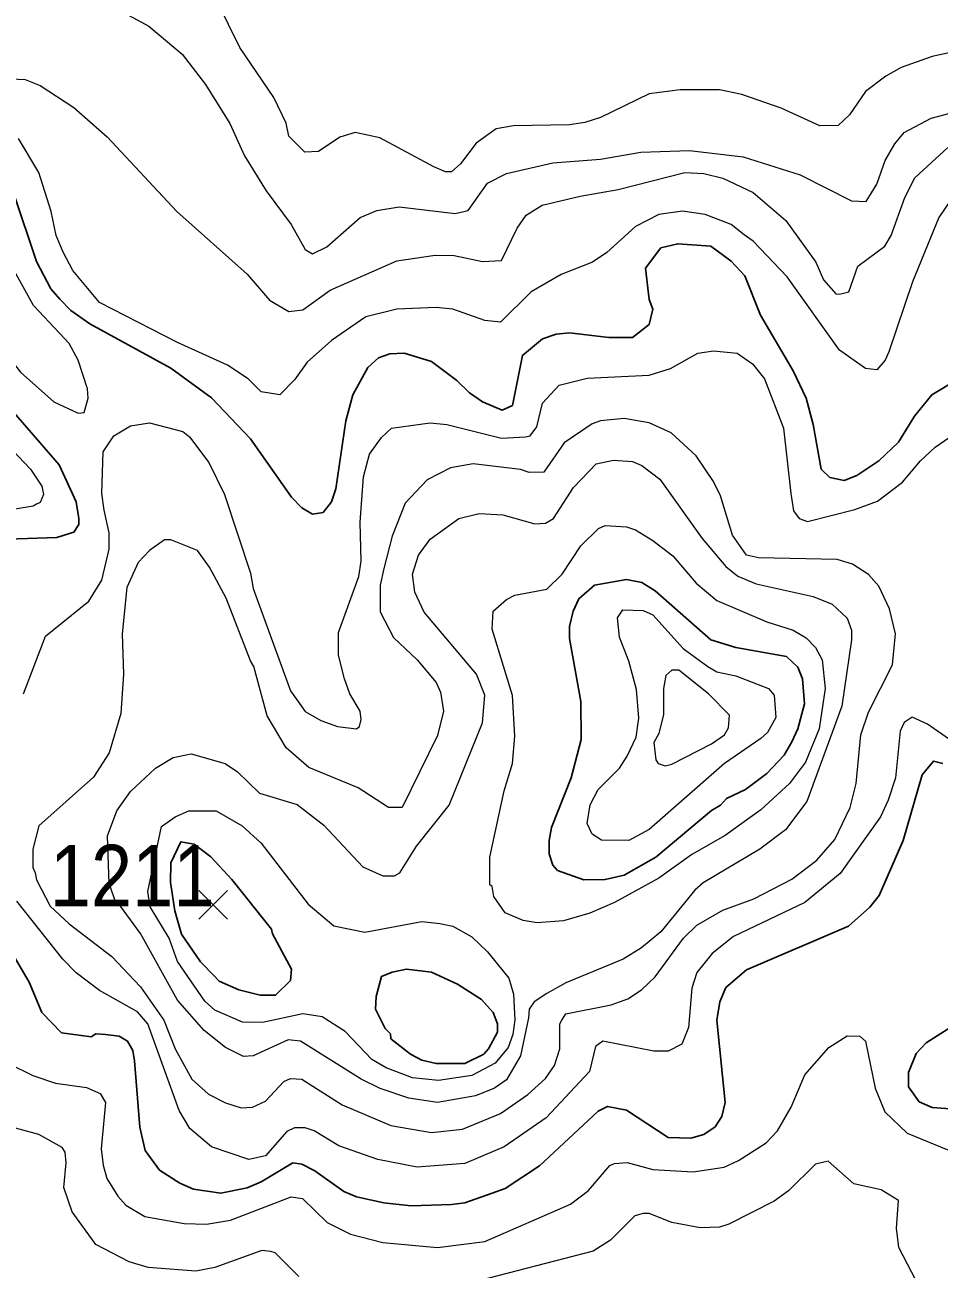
# Model space of a CAD drawing. Extents: x 423 to 448.8, y 7456.3 to 7484.
# Drawn here: x 429.044 to 430.233, y 7478.283 to 7479.901 of the extents above; entities that cross this region are included whole.
import ezdxf
from ezdxf.enums import TextEntityAlignment as Align

# ---------------------------------------------------------------- set-up
doc = ezdxf.new("R2010")
doc.units = 0
doc.header["$LTSCALE"] = 0.032
for name, color, linetype, lineweight in [('1', 7, 'Continuous', 25), ('2', 7, 'Continuous', 13), ('21', 7, 'Continuous', 25)]:
    doc.layers.add(name, color=color, linetype=linetype, lineweight=lineweight)
doc.layers.add('61', color=7, linetype='Continuous')

msp = doc.modelspace()

# ---------------------------------------------------------------- linework, layer by layer
at = {"layer": '1'}
for points in [[(429.3377, 7479.3629), (429.2867, 7479.4163), (429.2341, 7479.4549), (429.1289, 7479.5122), (429.1042, 7479.5299), (429.0895, 7479.5446), (429.0779, 7479.5578), (429.0593, 7479.5934), (429.0299, 7479.6816)], [(430.2597, 7479.4418), (430.2234, 7479.4201), (430.2009, 7479.3923), (430.1801, 7479.3583), (430.1546, 7479.3343), (430.1259, 7479.3149), (430.1097, 7479.3087), (430.0911, 7479.3126), (430.0795, 7479.3235), (430.0695, 7479.3815), (430.0602, 7479.4155), (430.0431, 7479.4511), (430.0006, 7479.5238), (429.9805, 7479.5748), (429.9627, 7479.5941), (429.9364, 7479.6135), (429.8931, 7479.6166), (429.8714, 7479.6112), (429.8513, 7479.5849), (429.856, 7479.5439), (429.8606, 7479.5315), (429.856, 7479.5114), (429.8343, 7479.4944), (429.8034, 7479.4944), (429.7524, 7479.5006), (429.7353, 7479.499), (429.7175, 7479.4928), (429.6912, 7479.4712), (429.6781, 7479.4062), (429.6649, 7479.4), (429.6394, 7479.4109), (429.6224, 7479.4225), (429.6061, 7479.4387), (429.5729, 7479.4635), (429.5373, 7479.4743), (429.5188, 7479.4735), (429.504, 7479.4681), (429.4901, 7479.4557), (429.4708, 7479.4202), (429.4615, 7479.3861), (429.4484, 7479.2979), (429.443, 7479.2809), (429.4321, 7479.267), (429.4182, 7479.2647), (429.4043, 7479.2732), (429.3911, 7479.2871), (429.3377, 7479.3629)], [(429.0044, 7479.4263), (429.0887, 7479.3289), (429.1111, 7479.2809), (429.1142, 7479.2593), (429.1142, 7479.2515), (429.1081, 7479.2415), (429.1034, 7479.2399), (429.0856, 7479.2345), (429.0222, 7479.2322)], [(429.6688, 7478.3876), (429.7136, 7478.4169), (429.7895, 7478.4881), (429.8019, 7478.4943), (429.8266, 7478.4896), (429.8808, 7478.4541), (429.9101, 7478.4533), (429.9272, 7478.458), (429.9418, 7478.468), (429.9504, 7478.4812), (429.955, 7478.4997), (429.9442, 7478.6065), (429.948, 7478.6304), (429.9557, 7478.649), (429.9828, 7478.6722), (430.1151, 7478.7287), (430.1429, 7478.7534), (430.1553, 7478.7689), (430.1863, 7478.8401), (430.211, 7478.9259), (430.2257, 7478.9437), (430.2381, 7478.9406)], [(429.0291, 7478.6916), (429.05, 7478.656), (429.0663, 7478.6165), (429.0918, 7478.5902), (429.1305, 7478.5848), (429.1367, 7478.5886), (429.1491, 7478.5879), (429.1668, 7478.5856), (429.1777, 7478.5794), (429.1846, 7478.567), (429.1869, 7478.5539), (429.1939, 7478.4673), (429.2008, 7478.4371), (429.2194, 7478.4115), (429.2457, 7478.3945), (429.2635, 7478.3868), (429.2991, 7478.3814), (429.3331, 7478.3883), (429.3517, 7478.3961), (429.3927, 7478.4208), (429.4043, 7478.4193), (429.4213, 7478.4108), (429.4592, 7478.3837), (429.4755, 7478.3767), (429.511, 7478.369), (429.5466, 7478.3651), (429.5992, 7478.3667), (429.6162, 7478.369), (429.6518, 7478.3814), (429.6688, 7478.3876)], [(430.2628, 7478.6065), (430.2164, 7478.577), (430.2032, 7478.5632), (430.1932, 7478.5384), (430.1932, 7478.5198), (430.2072, 7478.5005), (430.2242, 7478.4928), (430.2597, 7478.4904)]]:
    msp.add_lwpolyline(points, dxfattribs=at)
for points in [[(429.7988, 7478.7897), (429.8235, 7478.7952), (429.8645, 7478.8184), (429.9372, 7478.8795), (429.9488, 7478.8864), (429.9565, 7478.8949), (429.9813, 7478.9066), (430.0091, 7478.9274), (430.0315, 7478.9514), (430.0416, 7478.9685), (430.0494, 7478.9855), (430.0579, 7479.018), (430.0555, 7479.0504), (430.0494, 7479.0659), (430.0346, 7479.0798), (429.9689, 7479.0914), (429.9364, 7479.1015), (429.8637, 7479.1649), (429.8467, 7479.1757), (429.8266, 7479.1796), (429.7848, 7479.1726), (429.7647, 7479.1548), (429.757, 7479.1386), (429.7523, 7479.1185), (429.7523, 7479.103), (429.767, 7479.021), (429.7678, 7478.9715), (429.7547, 7478.922), (429.7291, 7478.8571), (429.726, 7478.8401), (429.726, 7478.823), (429.7307, 7478.8083), (429.7369, 7478.8014), (429.7709, 7478.789)], [(429.3663, 7478.719), (429.3648, 7478.7248), (429.3135, 7478.7894), (429.2862, 7478.819), (429.2645, 7478.8357), (429.2472, 7478.8386), (429.2342, 7478.8111), (429.2335, 7478.7858), (429.2393, 7478.749), (429.2481, 7478.7186), (429.2728, 7478.6823), (429.2898, 7478.6645), (429.2968, 7478.6575), (429.3223, 7478.6459), (429.3502, 7478.6389), (429.3703, 7478.6389), (429.3896, 7478.6583), (429.3911, 7478.673)], [(429.5219, 7478.6691), (429.5404, 7478.673), (429.5729, 7478.6691), (429.6069, 7478.6536), (429.6378, 7478.6335), (429.6533, 7478.6165), (429.6588, 7478.6018), (429.6588, 7478.591), (429.6471, 7478.5693), (429.641, 7478.5624), (429.6162, 7478.55), (429.5791, 7478.55), (429.5605, 7478.5546), (429.5458, 7478.5624), (429.5203, 7478.5825), (429.5195, 7478.5887), (429.5126, 7478.5956), (429.5002, 7478.6211), (429.501, 7478.6374), (429.508, 7478.6635)]]:
    msp.add_lwpolyline(points, close=True, dxfattribs=at)
at = {"layer": '2'}
for points in [[(430.286, 7479.8734), (430.2242, 7479.8602), (430.1839, 7479.8456), (430.1638, 7479.8347), (430.1375, 7479.8146), (430.1166, 7479.7844), (430.102, 7479.7705), (430.078, 7479.7698), (430.0277, 7479.793), (429.9767, 7479.8107), (429.9473, 7479.8169), (429.8962, 7479.8169), (429.856, 7479.8115), (429.7926, 7479.7806), (429.7725, 7479.7744), (429.7524, 7479.7713), (429.6797, 7479.7698), (429.6572, 7479.7659), (429.6309, 7479.7473), (429.6108, 7479.7203), (429.5992, 7479.7102), (429.5914, 7479.7102), (429.576, 7479.7164), (429.5056, 7479.7543), (429.4739, 7479.7612), (429.4538, 7479.755), (429.426, 7479.7365), (429.4081, 7479.7357), (429.3873, 7479.7566), (429.3842, 7479.7736), (429.3679, 7479.8069), (429.3238, 7479.8719), (429.279, 7479.9631)], [(429.1583, 7479.9252), (429.2055, 7479.8997), (429.2488, 7479.8633), (429.279, 7479.8239), (429.3107, 7479.7729), (429.33, 7479.7311), (429.3579, 7479.6854), (429.3903, 7479.6414), (429.4089, 7479.6089), (429.4182, 7479.6034), (429.4367, 7479.6127), (429.4801, 7479.6506), (429.5018, 7479.6599), (429.5311, 7479.6646), (429.6039, 7479.656), (429.6208, 7479.6599), (429.6456, 7479.6955), (429.6704, 7479.7079), (429.7307, 7479.7218), (429.7926, 7479.7264), (429.8452, 7479.7357), (429.9086, 7479.738), (429.9782, 7479.7295), (430.0525, 7479.7063), (430.119, 7479.6723), (430.1383, 7479.6715), (430.1522, 7479.694), (430.163, 7479.7249), (430.1754, 7479.7466), (430.1878, 7479.7612), (430.2226, 7479.7798), (430.3464, 7479.8123)], [(429.0168, 7479.8316), (429.0446, 7479.8301), (429.064, 7479.8223), (429.108, 7479.7937), (429.1513, 7479.7558), (429.2419, 7479.6583), (429.3331, 7479.5771), (429.3625, 7479.5431), (429.3873, 7479.5284), (429.4058, 7479.5307), (429.4414, 7479.5563), (429.5281, 7479.5942), (429.5776, 7479.6019), (429.6023, 7479.6011), (429.6394, 7479.5934), (429.6642, 7479.5949), (429.6843, 7479.6367), (429.6959, 7479.6537), (429.7168, 7479.6669), (429.7663, 7479.6785), (429.8158, 7479.687), (429.9024, 7479.7094), (429.9272, 7479.7079), (429.9519, 7479.7017)], [(430.2481, 7479.6738), (430.2326, 7479.6506), (430.1986, 7479.5671), (430.1677, 7479.4758), (430.163, 7479.465), (430.1522, 7479.4526), (430.1375, 7479.4541), (430.1035, 7479.4781), (430.0354, 7479.5733), (429.9913, 7479.6197), (429.9797, 7479.6282), (429.9627, 7479.6414), (429.9287, 7479.6545), (429.8993, 7479.6591), (429.8684, 7479.6545), (429.8382, 7479.639), (429.8011, 7479.605), (429.7825, 7479.5926), (429.7415, 7479.5764), (429.7028, 7479.5539), (429.6626, 7479.5145), (429.6425, 7479.5168), (429.6008, 7479.5315), (429.5791, 7479.5338), (429.5281, 7479.5315), (429.4878, 7479.5214), (429.443, 7479.4905), (429.4112, 7479.4627), (429.395, 7479.4395), (429.3757, 7479.4201), (429.3517, 7479.424), (429.3346, 7479.441), (429.3076, 7479.4588), (429.2426, 7479.4882), (429.1413, 7479.54), (429.1065, 7479.5818), (429.0941, 7479.6058), (429.0848, 7479.6274), (429.0786, 7479.6584), (429.0624, 7479.7094), (429.0361, 7479.7535)], [(429.9519, 7479.7017), (429.9913, 7479.6831), (430.0339, 7479.6468), (430.0726, 7479.5926), (430.0826, 7479.5694), (430.0989, 7479.5516), (430.1035, 7479.5508), (430.1158, 7479.5539), (430.1274, 7479.5872), (430.1623, 7479.6135), (430.1708, 7479.6274), (430.1886, 7479.6769), (430.2017, 7479.7024), (430.2443, 7479.7419)], [(429.0423, 7479.0311), (429.0709, 7479.1061), (429.1274, 7479.1517), (429.1444, 7479.1788), (429.1537, 7479.2191), (429.1537, 7479.2407), (429.1475, 7479.2701), (429.1444, 7479.2918), (429.1459, 7479.3459), (429.1599, 7479.3668), (429.1815, 7479.3799), (429.2063, 7479.3838), (429.2496, 7479.3722), (429.2581, 7479.3652), (429.2836, 7479.332), (429.3037, 7479.2902), (429.3378, 7479.1881), (429.3409, 7479.168), (429.3896, 7479.035), (429.4089, 7479.0079), (429.429, 7478.9963), (429.4507, 7478.9886), (429.4754, 7478.9854), (429.4793, 7478.9885), (429.4816, 7478.9978), (429.4801, 7479.0087), (429.4669, 7479.0311), (429.46, 7479.0504), (429.4522, 7479.0814), (429.4522, 7479.1108), (429.4785, 7479.1835), (429.4816, 7479.2036), (429.4801, 7479.2546), (429.4847, 7479.3134), (429.4924, 7479.3428), (429.5079, 7479.3644), (429.5211, 7479.3768), (429.5714, 7479.3838), (429.593, 7479.3815), (429.6642, 7479.3637), (429.6951, 7479.3652), (429.7013, 7479.3668), (429.7098, 7479.3783), (429.7175, 7479.4093), (429.7392, 7479.4325), (429.7756, 7479.4418), (429.856, 7479.4456), (429.8838, 7479.4541), (429.9194, 7479.4743), (429.9395, 7479.4774), (429.9705, 7479.4743), (429.9905, 7479.4603), (430.006, 7479.441), (430.0308, 7479.3768), (430.0401, 7479.2918), (430.0439, 7479.2693), (430.0509, 7479.2593), (430.0617, 7479.2554), (430.1236, 7479.2708), (430.153, 7479.2817), (430.1854, 7479.3064), (430.2087, 7479.3343), (430.228, 7479.352), (430.2976, 7479.4)], [(429.8637, 7478.6629), (429.9008, 7478.7132), (429.9179, 7478.7302), (429.9519, 7478.7495), (429.9921, 7478.7643), (430.0416, 7478.7898), (430.0741, 7478.8145), (430.0973, 7478.8416), (430.1174, 7478.8834), (430.1252, 7478.9143), (430.1313, 7478.9777), (430.1414, 7479.0071), (430.1723, 7479.069), (430.1762, 7479.1092), (430.1685, 7479.1417), (430.1545, 7479.1711), (430.1414, 7479.1865), (430.1205, 7479.1997), (430.1004, 7479.2059), (429.9983, 7479.2082), (429.9828, 7479.2113), (429.9643, 7479.2376), (429.9488, 7479.2887), (429.9395, 7479.3072), (429.9171, 7479.3405), (429.8846, 7479.3706), (429.856, 7479.3838), (429.8235, 7479.3892), (429.7926, 7479.3861), (429.7817, 7479.3822), (429.7454, 7479.3575), (429.7191, 7479.3196), (429.6998, 7479.3188), (429.6889, 7479.3227), (429.6271, 7479.3304), (429.5977, 7479.325), (429.5675, 7479.3095), (429.5389, 7479.2793), (429.5219, 7479.2361), (429.511, 7479.1943), (429.5064, 7479.1726), (429.5064, 7479.1378), (429.5234, 7479.1045), (429.5543, 7479.0752), (429.5791, 7479.0458), (429.5845, 7479.0334), (429.5884, 7479.0087), (429.5806, 7478.9769), (429.535, 7478.8834), (429.5172, 7478.8834), (429.4778, 7478.9089), (429.4136, 7478.9352), (429.3841, 7478.9607), (429.3594, 7479.0025), (429.3419, 7479.0668), (429.3378, 7479.0739), (429.306, 7479.1556), (429.2844, 7479.1959), (429.2689, 7479.2175), (429.2341, 7479.2314), (429.2256, 7479.2314), (429.2062, 7479.2175), (429.1916, 7479.202), (429.1769, 7479.1696), (429.1707, 7479.1092), (429.1723, 7479.0566), (429.1692, 7479.0056), (429.1537, 7478.9545), (429.1336, 7478.9228), (429.0624, 7478.8594), (429.0547, 7478.8292), (429.0547, 7478.8052), (429.0578, 7478.7983), (429.0593, 7478.789), (429.0771, 7478.7549), (429.1018, 7478.7317), (429.1575, 7478.6892), (429.1947, 7478.6498), (429.2248, 7478.6065), (429.2395, 7478.5693), (429.2612, 7478.5299), (429.2828, 7478.5105), (429.3053, 7478.4989), (429.3254, 7478.4927), (429.3401, 7478.4935), (429.3571, 7478.5012), (429.3811, 7478.5268), (429.3896, 7478.5307), (429.4043, 7478.5299), (429.4568, 7478.4966), (429.5203, 7478.4695), (429.5729, 7478.4603), (429.6131, 7478.4649), (429.6626, 7478.485), (429.6982, 7478.5098), (429.7214, 7478.5306), (429.733, 7478.5477), (429.74, 7478.5693), (429.74, 7478.6018), (429.7423, 7478.6065), (429.7477, 7478.615)], [(429.0207, 7479.3559), (429.0516, 7479.3235), (429.0663, 7479.301), (429.0686, 7479.2902), (429.0639, 7479.2801), (429.0594, 7479.278), (429.0548, 7479.275), (429.0006, 7479.2662)], [(430.2814, 7478.9475), (430.218, 7478.9916), (430.1979, 7479.0009), (430.1878, 7478.9939), (430.1824, 7478.9824), (430.1762, 7478.922), (430.1669, 7478.8927), (430.1568, 7478.871), (430.1043, 7478.7975), (430.0586, 7478.7596), (429.9658, 7478.7155), (429.938, 7478.6931), (429.9179, 7478.6684), (429.9117, 7478.6482), (429.907, 7478.5972), (429.8985, 7478.5755), (429.8808, 7478.5662), (429.8622, 7478.5662), (429.7956, 7478.5794), (429.7863, 7478.5724), (429.7786, 7478.54), (429.7222, 7478.4796), (429.6673, 7478.4417), (429.6162, 7478.42), (429.5544, 7478.4154), (429.5033, 7478.4255), (429.4523, 7478.4432), (429.4205, 7478.4626), (429.4089, 7478.4664), (429.395, 7478.4664), (429.3849, 7478.4618), (429.3571, 7478.4301), (429.3354, 7478.4255), (429.2867, 7478.4417), (429.2589, 7478.4657), (429.245, 7478.4889)], [(429.245, 7478.4889), (429.2039, 7478.6018), (429.1908, 7478.6173), (429.1413, 7478.6451), (429.1111, 7478.6683), (429.0934, 7478.6861), (429.0338, 7478.7612)], [(429.7477, 7478.615), (429.8065, 7478.6266), (429.8282, 7478.6343), (429.8459, 7478.6459), (429.8637, 7478.6629)], [(429.3904, 7478.3767), (429.4051, 7478.3744), (429.4375, 7478.3435), (429.4677, 7478.328), (429.5095, 7478.3172), (429.5807, 7478.311), (429.6425, 7478.3187), (429.7539, 7478.3674), (429.7771, 7478.3852), (429.8049, 7478.4177), (429.8111, 7478.42), (429.8274, 7478.4216), (429.8606, 7478.4123), (429.9132, 7478.4092), (429.9535, 7478.4154), (429.972, 7478.4239), (430.0083, 7478.4471), (430.0231, 7478.4626), (430.0408, 7478.4935), (430.0586, 7478.5353), (430.0896, 7478.5709), (430.1135, 7478.5864), (430.1298, 7478.5856), (430.1375, 7478.5794), (430.1499, 7478.5183), (430.1623, 7478.4874), (430.1917, 7478.4595), (430.2613, 7478.4309)], [(429.023, 7478.55), (429.0547, 7478.5345), (429.0841, 7478.5245), (429.1243, 7478.519), (429.1421, 7478.5113), (429.1491, 7478.4997), (429.1436, 7478.4394), (429.146, 7478.4178), (429.1506, 7478.4007), (429.1653, 7478.3775), (429.1753, 7478.3659), (429.2001, 7478.3512), (429.2512, 7478.3419), (429.2805, 7478.3412), (429.3115, 7478.3466), (429.3904, 7478.3767)], [(429.4004, 7478.2731), (429.3695, 7478.304), (429.3641, 7478.3056), (429.3525, 7478.3071), (429.2914, 7478.2847), (429.2666, 7478.2801), (429.2047, 7478.2847), (429.18, 7478.2924), (429.1366, 7478.3148), (429.1057, 7478.3574), (429.0949, 7478.3891), (429.098, 7478.4208), (429.0965, 7478.4348), (429.0926, 7478.441), (429.0624, 7478.458), (428.9758, 7478.4811)], [(430.2257, 7478.2243), (430.1808, 7478.311), (430.1778, 7478.3358), (430.1801, 7478.3721), (430.1577, 7478.386), (430.1221, 7478.3937), (430.0888, 7478.4232), (430.0725, 7478.4193), (430.037, 7478.3845), (430.0184, 7478.3713), (429.9596, 7478.3411), (429.9473, 7478.3373), (429.9225, 7478.3365), (429.8854, 7478.3435), (429.856, 7478.3551), (429.8483, 7478.3551), (429.8374, 7478.352), (429.8057, 7478.3203), (429.7833, 7478.3063), (429.6224, 7478.2646)]]:
    msp.add_lwpolyline(points, dxfattribs=at)
for points in [[(429.0895, 7479.4998), (429.0554, 7479.5362), (429.033, 7479.5771), (429.0191, 7479.5841), (429.0067, 7479.5841), (428.9912, 7479.5709), (428.9866, 7479.547), (428.9897, 7479.5346), (429.0191, 7479.4743), (429.0384, 7479.4495), (429.0817, 7479.4109), (429.1135, 7479.3961), (429.1212, 7479.3969), (429.1266, 7479.4155), (429.1258, 7479.4279), (429.1135, 7479.465), (429.1018, 7479.4867)], [(429.7075, 7479.2522), (429.7214, 7479.2531), (429.7315, 7479.2593), (429.7577, 7479.2995), (429.7871, 7479.3304), (429.8096, 7479.3351), (429.8343, 7479.3335), (429.8467, 7479.3281), (429.8699, 7479.3103), (429.9248, 7479.233), (429.9558, 7479.1966), (429.9712, 7479.1842), (429.9952, 7479.1742), (430.0695, 7479.1579), (430.0942, 7479.1479), (430.1135, 7479.1293), (430.119, 7479.1139), (430.119, 7479.1015), (430.1066, 7479.0149), (430.0609, 7478.8911), (430.0331, 7478.854), (429.9999, 7478.8292), (429.9264, 7478.7851), (429.9155, 7478.7758), (429.8714, 7478.7217), (429.8459, 7478.7008), (429.822, 7478.6861), (429.7477, 7478.6552), (429.723, 7478.6412), (429.7067, 7478.6304), (429.6998, 7478.6211), (429.699, 7478.6096), (429.6889, 7478.5601), (429.6704, 7478.5291), (429.6549, 7478.5183), (429.6302, 7478.5082), (429.5807, 7478.4997), (429.5435, 7478.5051), (429.5064, 7478.5175), (429.4816, 7478.5299), (429.4028, 7478.5794), (429.3865, 7478.5809), (429.3409, 7478.5601), (429.3285, 7478.5593), (429.3053, 7478.5709), (429.2774, 7478.5933), (429.2426, 7478.6328), (429.1947, 7478.7194), (429.1684, 7478.7549), (429.1634, 7478.7571), (429.1538, 7478.7843), (429.1518, 7478.8462), (429.1637, 7478.8787), (429.1815, 7478.9042), (429.214, 7478.9344), (429.2372, 7478.9483), (429.2604, 7478.953), (429.3045, 7478.9406), (429.3207, 7478.9298), (429.3494, 7478.9019), (429.3981, 7478.8872), (429.4329, 7478.8601), (429.4839, 7478.806), (429.5095, 7478.7944), (429.525, 7478.7944), (429.5319, 7478.7983), (429.5535, 7478.8331), (429.5961, 7478.8864), (429.6394, 7478.9932), (429.6425, 7479.0295), (429.6317, 7479.0566), (429.5636, 7479.1371), (429.5513, 7479.1634), (429.5482, 7479.1866), (429.5559, 7479.2113), (429.5713, 7479.2322), (429.6085, 7479.2593), (429.6348, 7479.2655), (429.6657, 7479.2639)], [(429.6704, 7479.154), (429.6812, 7479.1595), (429.723, 7479.1672), (429.7431, 7479.1866), (429.767, 7479.2236), (429.7902, 7479.2461), (429.7988, 7479.25), (429.8266, 7479.2484), (429.8382, 7479.2446), (429.8606, 7479.2306), (429.8869, 7479.2105), (429.9171, 7479.1749), (429.9441, 7479.1525), (430.0091, 7479.1247), (430.0432, 7479.1139), (430.0601, 7479.1038), (430.0725, 7479.0914), (430.0811, 7479.0751), (430.0849, 7479.0381), (430.0772, 7478.9855), (430.0594, 7478.9422), (430.0385, 7478.9143), (430.0014, 7478.8802), (429.955, 7478.847), (429.9117, 7478.8222), (429.8684, 7478.7913), (429.8111, 7478.7596), (429.7787, 7478.7457), (429.7446, 7478.7356), (429.7106, 7478.7333), (429.692, 7478.7364), (429.6688, 7478.7464), (429.6541, 7478.7674), (429.6518, 7478.7805), (429.6487, 7478.7828), (429.6487, 7478.8184), (429.6673, 7478.905), (429.6781, 7478.9406), (429.6812, 7478.9762), (429.6781, 7479.0288), (429.6518, 7479.1154), (429.6533, 7479.1386)], [(429.8296, 7479.0736), (429.8173, 7479.1046), (429.815, 7479.1301), (429.8219, 7479.1402), (429.8483, 7479.1394), (429.8606, 7479.134), (429.9001, 7479.0899), (429.9325, 7479.0667), (429.9441, 7479.0597), (429.9689, 7479.0543), (430.0114, 7479.0381), (430.0184, 7479.0295), (430.0207, 7479.0001), (430.0099, 7478.9808), (430.0014, 7478.9731), (429.9542, 7478.9406), (429.856, 7478.8547), (429.8297, 7478.8401), (429.7941, 7478.8408), (429.7817, 7478.8485), (429.7756, 7478.8625), (429.7794, 7478.8865), (429.7895, 7478.9066), (429.8173, 7478.9344), (429.8274, 7478.9499), (429.839, 7478.9746), (429.8428, 7478.9994), (429.8397, 7479.0365)], [(429.9372, 7478.9661), (429.9542, 7478.9777), (429.9594, 7478.9869), (429.9604, 7479.0032), (429.9333, 7479.0311), (429.8946, 7479.062), (429.8854, 7479.062), (429.8777, 7479.0551), (429.8746, 7479.0381), (429.8746, 7479.004), (429.8684, 7478.9793), (429.8622, 7478.9677), (429.8645, 7478.9453), (429.8676, 7478.9406), (429.8769, 7478.9375), (429.8854, 7478.9398)], [(429.2217, 7478.8586), (429.2395, 7478.871), (429.2573, 7478.8787), (429.2929, 7478.8787), (429.3269, 7478.8594), (429.3517, 7478.837), (429.4128, 7478.7573), (429.4461, 7478.7294), (429.4863, 7478.7209), (429.5605, 7478.7348), (429.5837, 7478.7325), (429.6008, 7478.7287), (429.6255, 7478.7148), (429.6456, 7478.6954), (429.6735, 7478.6614), (429.6796, 7478.6405), (429.6812, 7478.6072), (429.6788, 7478.5879), (429.6727, 7478.5709), (429.6556, 7478.5508), (429.6255, 7478.5345), (429.5822, 7478.5283), (429.5482, 7478.5314), (429.5141, 7478.5446), (429.4955, 7478.5554), (429.4607, 7478.5918), (429.4306, 7478.6111), (429.4058, 7478.615), (429.3533, 7478.6034), (429.327, 7478.6041), (429.2913, 7478.6196), (429.2782, 7478.6312), (429.2426, 7478.683), (429.2318, 7478.7132), (429.207, 7478.7542), (429.2041, 7478.774)]]:
    msp.add_lwpolyline(points, close=True, dxfattribs=at)
at = {"layer": '21'}
for p, q in [((429.2704, 7478.7753), (429.3079, 7478.7378)), ((429.3079, 7478.7753), (429.2704, 7478.7378))]:
    msp.add_line(p, q, dxfattribs=at)

# ---------------------------------------------------------------- texts
at = {"layer": '61', "width": 0.9}
msp.add_text('1211', height=0.08, dxfattribs=at).set_placement((429.1837, 7478.7546), align=Align.CENTER)

doc.saveas('drawing.dxf')
